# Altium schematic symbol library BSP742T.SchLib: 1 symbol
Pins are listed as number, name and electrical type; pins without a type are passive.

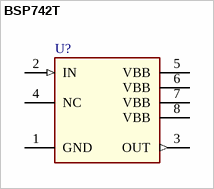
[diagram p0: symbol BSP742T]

## BSP742T
designator U?  (value not drawn)
Smart Power High-Side-Switch, VBB 41V, R(ON) 350mOhm; Manufacturer: Infineon Technologies
footprint SOIC127P600X175-8N-21
pins: 1 GND (power) "Logic Ground", 2 IN (in) "Input", 3 OUT (out) "Output to the Load", 4 NC "Not Connected", 5 VBB (power) "Positive Power Supply Voltage", 6 VBB (power) "Positive Power Supply Voltage", 7 VBB (power) "Positive Power Supply Voltage", 8 VBB (power) "Positive Power Supply Voltage"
